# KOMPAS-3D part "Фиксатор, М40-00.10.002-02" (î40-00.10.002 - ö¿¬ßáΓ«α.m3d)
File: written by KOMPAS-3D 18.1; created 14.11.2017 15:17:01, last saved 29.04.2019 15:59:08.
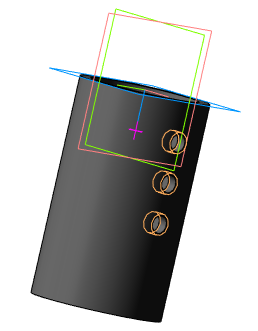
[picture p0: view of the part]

Document properties: Автор: Милов; Организация: Милов; Полное имя файла: D:\Разное Лифлянд\Переработка Лифлянд\Магна ins 40\М40-00.10.002 - Фиксатор.m3d

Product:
- Part/product: Фиксатор  | designation М40-00.10.002-02
    Материал: Сталь 12Х18Н10Т ГОСТ 5632-72 (density 7900 kg/m3)
    Масса: 0.346158
- Part/product: Фиксатор  | designation М40-00.10.002-01
    Материал: Сталь 12Х18Н10Т ГОСТ 5632-72 (density 7900 kg/m3)
    Масса: 0.344362
- Part/product: Фиксатор  | designation М40-00.10.002-02
    Материал: Сталь 12Х18Н10Т ГОСТ 5632-72 (density 7900 kg/m3)
    Масса: 0.346156
    Раздел спецификации: Детали
    Форматы листов документа: A3
    source file: М40-00.10.002 - Фиксатор.cdw

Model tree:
1. Эскиз:1
2. Операция выдавливания:1
     Расстояние 1 = 80
3. Эскиз:2
4. Отверстие:1  (labels: M8)
     Глубина выреза = 24; Диаметр отверстия = 6.64684; Угол конуса торца = 118; Координата X = -15
5. M8  (with: Отверстие:1, Операция выдавливания:1)  (labels: cil0_24705-2004 coarse)
     Длина резьбы = 24; Шаг резьбы = 1.25; Номинальный диаметр резьбы = 8
6. Массив по сетке:1  (with: Отверстие:1, Эскиз:2)  (labels: M8)  (2 pattern instances)
7. Отверстие:1  (with: Эскиз:2)  (labels: M8)
8. Эскиз:3  (with: Операция выдавливания:1)
9. Отверстие:3  (labels: M6)
     Глубина выреза = 40; Диаметр отверстия = 4.91747; Угол конуса торца = 118; Расстояние 1 = -74
10. M6  (with: Отверстие:3, Операция выдавливания:1)  (labels: cil0_24705-2004 coarse)
     Длина резьбы = 24; Шаг резьбы = 1; Номинальный диаметр резьбы = 6
11. Массив по концентрической сетке:3  (with: Отверстие:3, Эскиз:3)  (2 pattern instances)
12. Отверстие:3  (with: Эскиз:3)
13. Эскиз:4
14. Вырезать элемент вращения:1  (labels: Сталь 12Х18Н10Т ГОСТ 5632-72)
     Угол 1 = 360
15. Отверстие:2
     Глубина выреза = 24; Диаметр отверстия = 4.91747; Угол конуса торца = 118; Координата X = -74
16. M6  (labels: cil0_24705-2004 coarse)
     Длина резьбы = 24; Шаг резьбы = 1; Номинальный диаметр резьбы = 6
17. Массив по концентрической сетке:2  (with: Отверстие:2)  (2 pattern instances)
18. Отверстие:2

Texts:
  Шаг 1
  Режим 1
  Направление 1
  Шаг 2
  Режим 2
  Направление 2
  Номер 1
  Номер 2
  Шаг по оси

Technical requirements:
  Gost Type A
